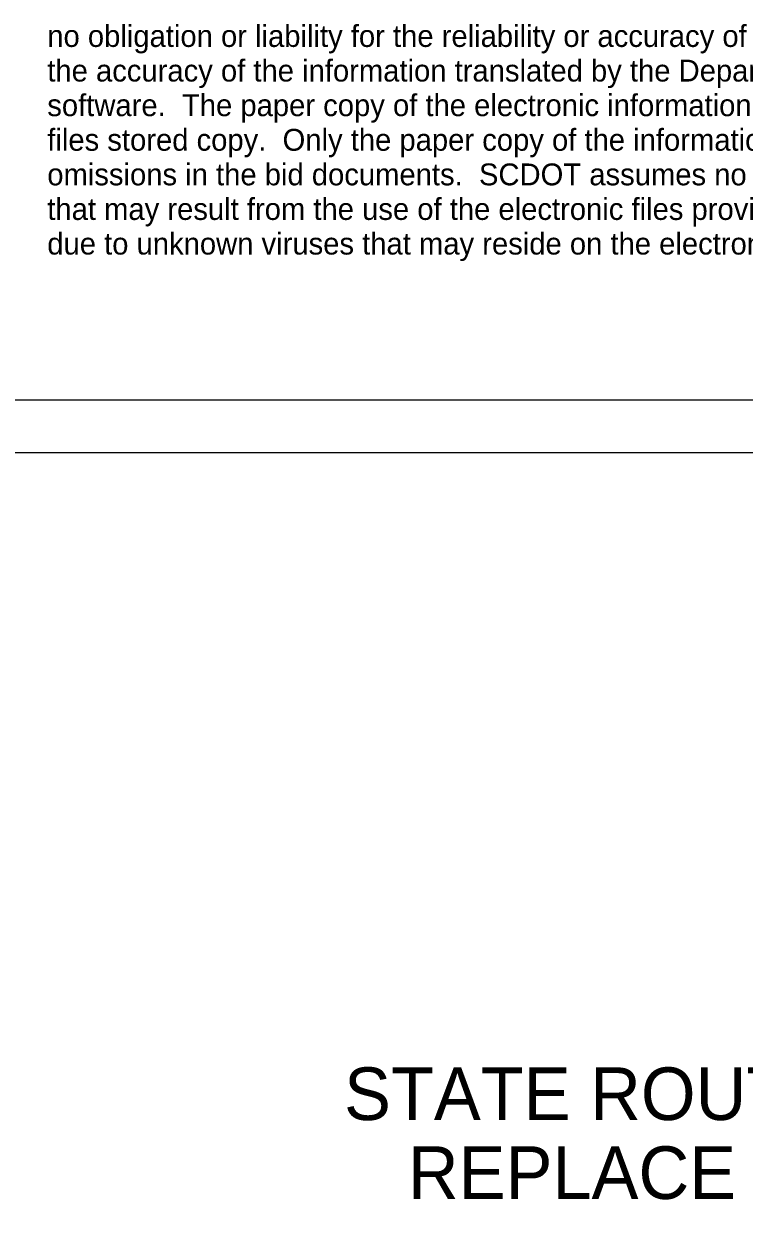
# Model space of a CAD drawing. Extents: x -2.9 to 3.9, y -2.5 to 1.79.
# Drawn here: x 0.71 to 1.281, y -1.316 to -0.369 of the extents above; entities that cross this region are included whole.
import ezdxf

# ---------------------------------------------------------------- set-up
doc = ezdxf.new("R2010")
doc.units = 0
for name, color, linetype in [('BR_BORDER LINES', 7, 'Continuous'), ('BR_DETAILS', 7, 'Continuous'), ('BR_USER NOTES', 7, 'Continuous'), ('NoPlot', 7, 'Continuous')]:
    doc.layers.add(name, color=color, linetype=linetype)

msp = doc.modelspace()

# ---------------------------------------------------------------- linework, layer by layer
at = {"layer": 'BR_BORDER LINES'}
msp.add_line((0.16667, -0.70822), (2.95833, -0.70822), dxfattribs=at)
at = {"layer": 'NoPlot'}
msp.add_lwpolyline([(0, -0.66667), (3, -0.66667), (3, -2.5), (0, -2.5)], close=True, dxfattribs=at)

# ---------------------------------------------------------------- texts
at = {"layer": 'BR_DETAILS'}
for s, p in [('STATE ROUTE S-39-32 (SHADY GROVE RD)', (0.96381, -1.23696)), ('REPLACE BRIDGE OVER CROW CREEK', (1.01443, -1.29946))]:
    msp.add_text(s, height=0.0416667, dxfattribs=at).set_placement(p)
at = {"layer": 'BR_USER NOTES'}
for s, height, p in [('no obligation or liability for the reliability or accuracy of the information contained herein: or for', 0.01730492, (0.72861, -0.38707)), ("the accuracy of the information translated by the Department's software for use with end user's", 0.0173049, (0.72861, -0.41447)), ('software.  The paper copy of the electronic information provided shall govern over the electronic', 0.0173049, (0.72861, -0.44188)), ('files stored copy.  Only the paper copy of the information may be used to determine errors and', 0.0173049, (0.72861, -0.46928)), ('omissions in the bid documents.  SCDOT assumes no liability for hardware or software damage', 0.0173049, (0.72861, -0.49668)), ('that may result from the use of the electronic files provided on disk, tape or by electronic transfer', 0.01730492, (0.72861, -0.52408)), ('due to unknown viruses that may reside on the electronic media when transferred to the end user.', 0.0173049, (0.72861, -0.55149))]:
    msp.add_text(s, height=height, rotation=360, dxfattribs=at).set_placement(p)

doc.saveas('drawing.dxf')
